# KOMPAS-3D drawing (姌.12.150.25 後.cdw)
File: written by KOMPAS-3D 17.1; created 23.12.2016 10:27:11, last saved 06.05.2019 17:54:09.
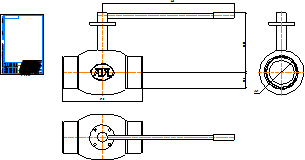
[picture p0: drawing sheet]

Sheet 1: A4, portrait

Title block, sheet 1: name: КШ.12.150.25 сс; material: Внимание! Данный продукт является объектом авторского права ООО «Торговый Дом АДЛ». / Запрещается изменение, копирование, распространение / (в том числе путем копирования на другие сайты и ресурсы в Интернете) / или любое иное использование информации и объектов без предварительного / согласия правообладателя (ООО «Торговый Дом АДЛ»).; sheets: 1; organisation: ООО "Торговый дом АДЛ"; sheet format: A4; stored path: C:\Users\tra\Desktop\2д чертежи\Шаровые краны БИВАЛ\КШ_Бивал_серия_11_12\KOMPAS_2D\КШ.12.150.25 сс.cdw

Views: Вид 1, Проекционный вид 2, Проекционный вид 3
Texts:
  Klimkovich
  ADL
Dimensions and other numbers on the sheet: 390; 645; 291,6; 79,5; 149; 1:1; 1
